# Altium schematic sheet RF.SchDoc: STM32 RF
size A4; Date: Not used; ApprovedBy: Not used; CheckedBy: Not used; Author: Not used; CompanyName: STMicroelectronics; DrawnBy: Not used; Engineer: Not used; Organization: Not used; Address1: Not used; Address2: Not used; Address3: Not used; Address4: Not used; DocumentNumber: Not used; Revision: Not used; SheetNumber: 5; SheetTotal: 5
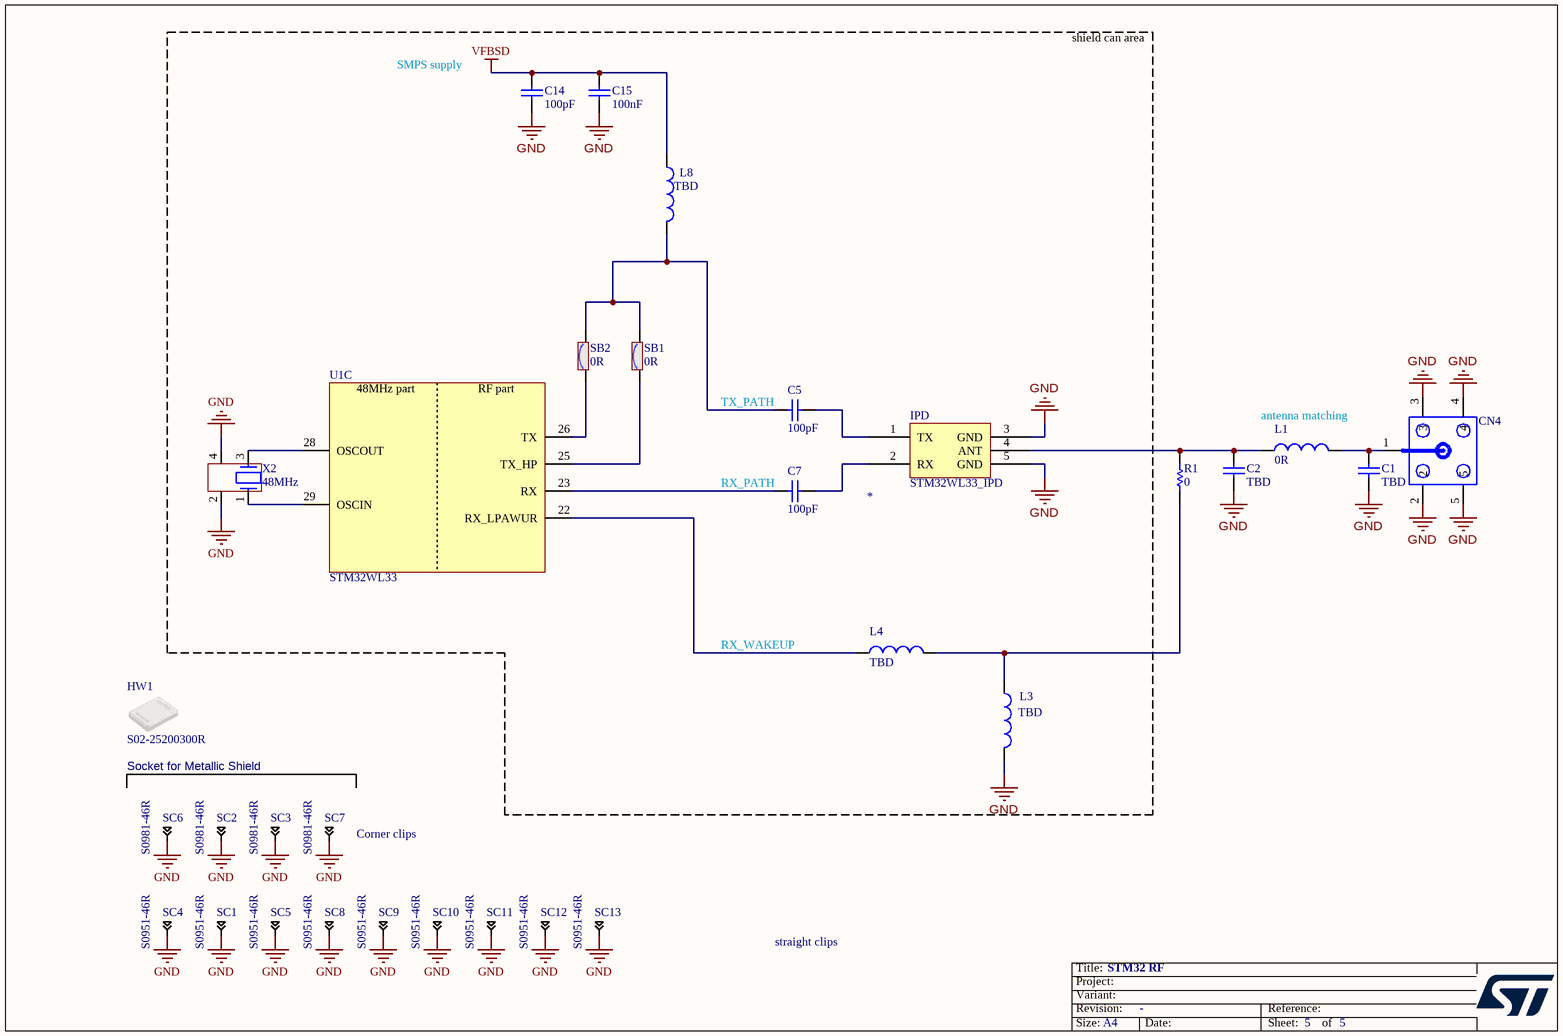
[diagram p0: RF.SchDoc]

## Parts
C1  value TBD  [GRM155--GJM155-0_05-MFG]  (hidden comment: Capacitor)
C2  value TBD  [GRM155--GJM155-0_05-MFG]  (hidden comment: Capacitor)
C5  value 100pF  [GRM155--GJM155-0_05-MFG]  (hidden comment: Capacitor)
C7  value 100pF  [GRM155--GJM155-0_05-MFG]  (hidden comment: Capacitor)
C14  value 100pF  [GRM155--GJM155-0_05-MFG]  (hidden comment: Capacitor)
C15  value 100nF  [GRM155--GJM155-0_05-MFG]  (hidden comment: Capacitor)
CN4  mmcx  [CON_SMA-RF_CINCH_142-0701-851]  (value not drawn)
HW1  value S02-25200300R  [SHIELD_HARWIN_S02-25200300_15X20_H3]  (hidden comment: S02-20150300)
IPD  STM32WL33_IPD  [STM32WL33_IPD]
L1  value 0R  [L0402]  (hidden comment: Inductor)
L3  value TBD  [L0402]  (hidden comment: Inductor)
L4  value TBD  [L0402]  (hidden comment: Inductor)
L8  value TBD  [LQW15AN_00-W0_6-0_1-MFG]  (hidden comment: Inductor)
R1  value 0  [GRM155--GJM155-0_05-MFG]  (hidden comment: Resistor)
SB1  value 0R  [SOLDER-BRIDGE_R0201_0R]  (hidden comment: SB_ON)
SB2  value 0R  [SOLDER-BRIDGE_R0201_0R]  (hidden comment: SB_ON)
SC1  value S0951-46R  [CLIP_HARWIN_S0951-46R]  (hidden comment: Shield-clip_S0951-46R)
SC2  value S0981-46R  [CLIP_HARWIN_S0981-46R]  (hidden comment: Shield-clip_S0951-46R)
SC3  value S0981-46R  [CLIP_HARWIN_S0981-46R]  (hidden comment: Shield-clip_S0951-46R)
SC4  value S0951-46R  [CLIP_HARWIN_S0951-46R]  (hidden comment: Shield-clip_S0951-46R)
SC5  value S0951-46R  [CLIP_HARWIN_S0951-46R]  (hidden comment: Shield-clip_S0951-46R)
SC6  value S0981-46R  [CLIP_HARWIN_S0981-46R]  (hidden comment: Shield-clip_S0951-46R)
SC7  value S0981-46R  [CLIP_HARWIN_S0981-46R]  (hidden comment: Shield-clip_S0951-46R)
SC8  value S0951-46R  [CLIP_HARWIN_S0951-46R]  (hidden comment: Shield-clip_S0951-46R)
SC9  value S0951-46R  [CLIP_HARWIN_S0951-46R]  (hidden comment: Shield-clip_S0951-46R)
SC10  value S0951-46R  [CLIP_HARWIN_S0951-46R]  (hidden comment: Shield-clip_S0951-46R)
SC11  value S0951-46R  [CLIP_HARWIN_S0951-46R]  (hidden comment: Shield-clip_S0951-46R)
SC12  value S0951-46R  [CLIP_HARWIN_S0951-46R]  (hidden comment: Shield-clip_S0951-46R)
SC13  value S0951-46R  [CLIP_HARWIN_S0951-46R]  (hidden comment: Shield-clip_S0951-46R)
U1  STM32WL33  [ICC_QFN48-EPAD-4P5X4P5_6X6_P040]  (part C of 3)
X2  value 48MHz  [CRY_NX1612SA_4P]  (hidden comment: XTAL_4_PINS)

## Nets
GND: C1.1 C2.1 C14.2 C15.1 CN4.2 CN4.3 CN4.4 CN4.5 IPD.3(GND) IPD.5(GND) L3.2 SC1.1 SC2.1 SC3.1 SC4.1 SC5.1 SC6.1 SC7.1 SC8.1 SC9.1 SC10.1 SC11.1 SC12.1 SC13.1 X2.2 X2.4
VFBSD: C14.1 C15.2 L8.1
NetC1_2: C1.2 CN4.1 L1.2
NetC2_2: C2.2 IPD.4(ANT) L1.1 R1.2
NetC5_1: C5.1 L8.2 SB1.2 SB2.2
NetC5_2: C5.2 IPD.1(TX)
NetC7_1: C7.1 U1.23(RX)
NetC7_2: C7.2 IPD.2(RX)
NetL3_1: L3.1 L4.2 R1.1
NetL4_1: L4.1 U1.22(RX_LPAWUR)
NetSB1_1: SB1.1 U1.25(TX_HP)
NetSB2_1: SB2.1 U1.26(TX)
NetU1_28: U1.28(OSCOUT) X2.3
NetU1_29: U1.29(OSCIN) X2.1

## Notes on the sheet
- shield can area
- SMPS supply
- (near C5) TX_PATH
- antenna matching
- (near C7) RX_PATH
- RX_WAKEUP
- Socket for Metallic Shield
- (near SC7) Corner clips
- straight clips

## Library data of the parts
C1 C2 = MCD-01600: Capacitor, MLCC, 1pF, 50V, NPO, +/-0.1pF, 0402, T=0.5mm; Part_Preference: Recommended; Manufacturer: YAGEO; Component_Country_Of_Origin: China; ShowFields: YES; ID: 3700
C5 C7 C14 = MCD-03446: Capacitor, MLCC, 100pF, 50V, COG, 1%, 0402, T=0.5mm; Part_Preference: Recommended; Manufacturer: MURATA; Manufacturer_Part_Number: GCM1555C1H101FA16; Order_Code_RS: 247-7780; ShowFields: YES; ID: 5562
C15 = MCD-03442: Capacitor, MLCC, 100nF, ±10%, X7R, 25V, 0402, T=0.5mm; Part_Preference: Recommended; Manufacturer: MURATA; Manufacturer_Part_Number: GRM155R71E104KE14D; Order_Code_RS: 247-8011; ShowFields: YES; ID: 5558
CN4 = MCD-02072: Jack_SMA, VR, PCB edge, 50R, T=7.92mm; Part_Type: Connector; Part_Preference: Recommended; Manufacturer: CINCH; Manufacturer_Part_Number: 142-0711-881; Order_Code_RS: 885-7532; Component_Country_Of_Origin: United States; ShowFields: YES; ID: 4172
HW1 = MCD-03503: RFI shield CAN, 25x20x3mm; Part_Type: Misc; Part_Preference: Recommended; Manufacturer: HARWIN; Order_Code_RS: 247-9196; Component_Country_Of_Origin: UK°; ShowFields: YES; ID: 5619
IPD = STM32WL33_IPD: IPD for STM32WL3; Manufacturer: STMICROELECTRONICS
L1 = MCD-01937: Resistor, 0R, 0402, +/-5%, 1/16W; Part_Preference: Recommended; Manufacturer: YAGEO; Manufacturer_Part_Number: RC0402JR-070RL; Order_Code_RS: 618-5804; Component_Country_Of_Origin: China; ShowFields: YES; ID: 4037
L3 = MCD-03462: Inductor, MLCC, 5.6nH, ±0.3nH, 650mA, 180mR, 0402, T=0.5mm; Part_Preference: Recommended; Manufacturer: MURATA; Order_Code_RS: 124-8165; ShowFields: YES; ID: 5578
L4 = MCD-03461: Inductor, 6.8nH, +/-3%, 0.6A, 220mR, 0402, T=0.5mm; Manufacturer: MURATA
L8 = MCD-03456: Inductor, Wire-wound, 12nHH, ±2%, 500mA, 1405mR, 0402, T=0.5mm; Part_Preference: Recommended; Manufacturer: MURATA; Order_Code_RS: 167-4829; ShowFields: YES; ID: 5572
R1 = MCD-03301: 0 ohm resistor; Part_Preference: Alternate; Manufacturer: YAGEO; Manufacturer_Part_Number: RT0402FRE07100KL; Alternate_EMS: M; ShowFields: YES; ID: 5417
SB1 SB2 = MCD-03219: Resistor, 0R, 0201, Solder Bridge ON , 1/20W,; Part_Type: Misc; Part_Preference: Recommended; Manufacturer: YAGEO; Manufacturer_Part_Number: RC0201JR-070RL; Order_Code_RS: 198-7623; Component_Country_Of_Origin: China; ShowFields: YES; ID: 5335
SC1 SC4 SC5 SC8 = MCD-01587: shield clip Harwin S0951-46R to fix RF shielded cavity; Part_Type: Misc; Part_Preference: Recommended; Component_Country_Of_Origin: South Korea
SC2 SC3 SC6 SC7 = MCD-02164: shield clip Harwin S0981-46R to fix RF shielded cavity - SMT RFI Shield Clip, Corner (T+R); Part_Type: Misc; Part_Preference: Recommended; Order_Code_RS: 161-3702; Component_Country_Of_Origin: South Korea; ShowFields: YES; ID: 4264
SC9-SC13 = MCD-01587: RFI shield clip mini TIN SMD; Part_Type: Mechanical; Part_Preference: Recommended; Manufacturer: HARWIN; Component_Country_Of_Origin: South Korea; ShowFields: YES; ID: 3687
U1 = MCD-03488: IC, Programmable Sub-1GHz wireless SoC; Part_Preference: Recommended; Manufacturer: STMICROELECTRONICS; Component_Country_Of_Origin: Unknown; ShowFields: YES; ID: 5604
X2 = MCD-03559: Crystal, 48MHz, 8pF, +/-10 ppm, 22R, 1.6x1.2mm; Part_Type: Crystal_Osc; Part_Preference: Recommended; Manufacturer: NDK; Manufacturer_Part_Number: NX1612SA-48.000 MHz-EXS00A-CS12140; ShowFields: YES; ID: 5675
